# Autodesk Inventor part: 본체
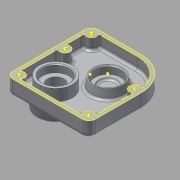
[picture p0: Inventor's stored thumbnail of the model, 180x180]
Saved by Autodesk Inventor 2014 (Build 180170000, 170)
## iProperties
Created: 2015-10
Part Number: 본체
Material: 알루미늄 6061
Document SubType Name: Modeling
Designer: youjin16
Density: 2.71 g/cm^3
Appearance: 알루미늄 - 평지
Mass: 265.675 g
Surface Area: 404.309 cm^2
Volume: 98.0352 cm^3
Author: youjin16
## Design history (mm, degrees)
sketch "스케치1"
  geometry: L1 (-42, 51.5)-(50, 51.5); L2 (50, 51.5)-(50, -43.5); L3 (42, -51.5)-(-42, -51.5); L4 (-50, -43.5)-(-50, 43.5); L5 (-50, 51.5)-(50, -51.5); L6 (50, 51.5)-(-50, -51.5); A1 r 8 centre (-42, 43.5) between (-42, 51.5) and (-50, 43.5); A2 r 8 centre (-42, -43.5) between (-50, -43.5) and (-42, -51.5); A3 r 8 centre (42, -43.5) between (42, -51.5) and (50, -43.5); 1 further point
  constraints: 12 end point, 6 point on circle, 6 point on line, 6 tangent, 3 centre point, 2 equal radius, 2 midpoint, 2 parallel, 1 horizontal, 1 perpendicular
  dimensions: "d0" = 100 distance of L5.end L6.end; "d1" = 103 distance of L6.end L5.start; "d2" = 8 radius of A1
extrude "돌출1" new body sketch "스케치1" distance "d3" = 18; taper "d4" = 0 deg
sketch "스케치2"
  geometry: L1 (50, 51.5)-(-42, 51.5) reference; L2 (-50, 43.5)-(-50, -43.5) reference; L3 (-42, -51.5)-(42, -51.5) reference; L4 (50, -43.5)-(50, 51.5) reference; L5 (-37.528, -47.5)-(37.528, -47.5); L6 (-46, -39.028)-(-46, 39.028); L7 (46, -39.028)-(46, 51.5); L8 (-37.528, 47.5)-(46, 47.5); L9 (-42, 17.5)-(-46, 17.5); L10 (-42, 5.5)-(-46, 5.5); L11 (42, 5.5)-(46, 5.5); L12 (42, 17.5)-(46, 17.5); A1 r 8 centre (-42, 43.5) between (-42, 51.5) and (-50, 43.5) reference; A2 r 8 centre (-42, -43.5) between (-50, -43.5) and (-42, -51.5) reference; A3 r 8 centre (42, -43.5) between (42, -51.5) and (50, -43.5) reference; A4 r 6 centre (-42, 43.5) between (-46, 39.028) and (-37.528, 47.5); A5 r 6 centre (-42, -43.5) between (-46, -39.028) and (-37.528, -47.5); A6 r 6 centre (42, -43.5) between (37.528, -47.5) and (46, -39.028); A7 r 6 centre (-42, 11.5) between (-42, 17.5) and (-42, 5.5); A8 r 6 centre (42, 11.5) between (42, 5.5) and (42, 17.5); 1 further point
  constraints: 16 end point, 10 point on circle, 6 perpendicular, 6 point on line, 5 centre point, 4 tangent, 3 coincident, 2 parallel, 2 vertical alignment
  dimensions: "d5" = 12 diameter of A4; "d6" = 12 diameter of A5; "d7" = 12 diameter of A6; "d8" = 4 distance between parallel lines of L3 L5; "d9" = 4 distance between parallel lines of L2 L6; "d10" = 4 distance between parallel lines of L8 L1; "d11" = 4 distance between parallel lines of L4 L7; "d16" = 12 diameter of A7; "d17" = 63 distance from line of L3 A7.centre; "d18" = 12 diameter of A8; "d19" = 63 distance from line of L3 A8.centre
extrude "돌출2" cut sketch "스케치2" distance "d12" = 4; taper "d13" = 0 deg
extrude "돌출3" join sketch "스케치2" stored distance "d20" = 4; taper "d21" = 0 deg
extrude "돌출4" join sketch "스케치2" distance "d22" = 4; taper "d23" = 0 deg
extrude "돌출5" join sketch "스케치2" distance "d24" = 4; taper "d25" = 0 deg
fillet "모깎기1" dims "d31" = 40
sketch "스케치5"
  geometry: L1 (46, 28.936)-(46, 17.5) reference; L2 (46, 17.5)-(42, 17.5) reference; L3 (42, 5.5)-(46, 5.5) reference; L4 (-37.528, 47.5)-(27.436, 47.5) reference; L5 (10, 51.5)-(-42, 51.5) reference; A1 r 6 centre (42, 11.5) between (42, 17.5) and (42, 5.5) reference; A2 r 40 centre (10, 11.5) between (27.436, 47.5) and (10, 51.5) reference; A3 r 36 centre (10, 11.5) between (10, 47.5) and (45.496, 5.5); A4 r 40 centre (10, 11.5) between (10, 51.5) and (46, 28.936); A5 r 36 centre (10, 11.5) between (45.496, 17.5) and (10, 47.5); A6 r 40 centre (10, 11.5) between (27.436, 47.5) and (10, 51.5); A7 r 40 centre (10, 11.5) between (46, 28.936) and (27.436, 47.5); A8 r 36 centre (10, 11.5) between (45.496, 5.5) and (45.688, 16.233); A9 r 36 centre (10, 11.5) between (45.688, 16.233) and (45.496, 17.5); 1 further point
  constraints: 15 point on circle, 7 centre point, 3 end point, 3 point on line, 2 coincident
  dimensions: "d32" = 72 diameter of A3
extrude "돌출7" join sketch "스케치5" stored distance "d33" = 10; taper "d34" = 0 deg
sketch "스케치6"
  geometry: C1 r 4 at (42, 43.5); C2 r 4 at (42, 11.5); C3 r 4 at (42, -43.5); C4 r 4 at (-42, -43.5); C5 r 4 at (-42, 11.5); A1 r 6 centre (42, 43.5) between (37.528, 47.5) and (46, 39.028) reference; A2 r 6 centre (42, -43.5) between (46, -39.028) and (37.528, -47.5) reference; A3 r 6 centre (42, 11.5) between (42, 17.5) and (42, 5.5) reference; A4 r 6 centre (-42, -43.5) between (-37.528, -47.5) and (-46, -39.028) reference; A5 r 6 centre (-42, 11.5) between (-42, 5.5) and (-42, 17.5) reference; 1 further point
  constraints: 5 centre point, 5 coincident
  dimensions: "d35" = 8 diameter of C1; "d36" = 8 diameter of C2; "d37" = 8 diameter of C3; "d38" = 8 diameter of C4; "d39" = 8 diameter of C5
extrude "돌출8" cut sketch "스케치6" distance "d40" = 4.4; taper "d41" = 0 deg
sketch "스케치7"
  geometry: C1 r 4 at (0, 0) reference; C2 r 4 at (0, 55) reference; C3 r 4 at (0, 87) reference; C4 r 4 at (-84, 55) reference; C5 r 4 at (-84, 0) reference; C6 r 2.25 at (0, 0); C7 r 2.25 at (0, 55); C8 r 2.25 at (0, 87); C9 r 2.25 at (-84, 55); C10 r 2.25 at (-84, 0); 1 further point
  constraints: 5 centre point, 5 coincident
  dimensions: "d42" = 4.5 diameter of C6; "d43" = 4.5 diameter of C7; "d44" = 4.5 diameter of C8; "d45" = 4.5 diameter of C9; "d46" = 4.5 diameter of C10
extrude "돌출9" cut sketch "스케치7" stored distance "d47" = 4.4; taper "d48" = 0 deg
sketch "스케치8"
  geometry: L1 (10, 51.5)-(-42, 51.5) reference; L2 (-50, 43.5)-(-50, -43.5) reference; L3 (-42, -51.5)-(42, -51.5) reference; L4 (50, -43.5)-(50, 11.5) reference; L5 (45.496, 17.5)-(42, 17.5) reference; L6 (42, 5.5)-(46, 5.5) reference; L7 (46, 5.5)-(46, -39.028) reference; L8 (37.528, -47.5)-(-37.528, -47.5) reference; L9 (-46, -39.028)-(-46, 5.5) reference; L10 (-46, 5.5)-(-42, 5.5) reference; L11 (-42, 17.5)-(-46, 17.5) reference; L12 (-46, 17.5)-(-46, 39.028) reference; L13 (-37.528, 47.5)-(10, 47.5) reference; C1 r 2.25 at (42, 11.5) reference; C2 r 2.25 at (-42, 11.5) reference; C3 r 2.25 at (-42, -43.5) reference; C4 r 2.25 at (-42, 43.5) reference; C5 r 2.25 at (42, -43.5) reference; A1 r 40 centre (10, 11.5) between (50, 11.5) and (10, 51.5) reference; A2 r 8 centre (-42, 43.5) between (-42, 51.5) and (-50, 43.5) reference; A3 r 8 centre (-42, -43.5) between (-50, -43.5) and (-42, -51.5) reference; A4 r 8 centre (42, -43.5) between (42, -51.5) and (50, -43.5) reference; A5 r 6 centre (42, 11.5) between (42, 17.5) and (42, 5.5) reference; A6 r 6 centre (42, -43.5) between (46, -39.028) and (37.528, -47.5) reference; A7 r 6 centre (-42, -43.5) between (-37.528, -47.5) and (-46, -39.028) reference; A8 r 6 centre (-42, 11.5) between (-42, 5.5) and (-42, 17.5) reference; A9 r 6 centre (-42, 43.5) between (-46, 39.028) and (-37.528, 47.5) reference; A10 r 36 centre (10, 11.5) between (45.496, 17.5) and (10, 47.5) reference; 1 further point
sketch "스케치9"
  geometry: 1 further point
sketch "스케치11"
  geometry: L1 (-50, 43.5)-(-50, -43.5) reference; L2 (-42, -51.5)-(42, -51.5) reference; C1 r 20 at (-20, -21.5); 1 further point
  constraints: 1 centre point
  dimensions: "d49" = 40 diameter of C1; "d50" = 30 distance from line of C1.centre L1; "d51" = 30 distance from line of C1.centre L2
extrude "돌출10" join sketch "스케치11" stored distance "d52" = 4.4; taper "d53" = 0 deg
sketch "스케치24"
  geometry: L1 (-37.528, 47.5)-(10, 47.5) reference; L2 (-46, 17.5)-(-46, 39.028) reference; L3 (-46, 17.5)-(-42, 17.5) reference; L4 (-42, 5.5)-(-46, 5.5) reference; L5 (-46, -39.028)-(-46, 5.5) reference; L6 (37.528, -47.5)-(-37.528, -47.5) reference; L7 (46, 5.5)-(46, -39.028) reference; L8 (46, 5.5)-(42, 5.5) reference; L9 (42, 17.5)-(45.496, 17.5) reference; C1 r 20 at (-20, -21.5) reference; C2 r 20 at (10, 11.5) reference; A1 r 36 centre (10, 11.5) between (45.496, 17.5) and (10, 47.5) reference; A2 r 6 centre (-42, 43.5) between (-46, 39.028) and (-37.528, 47.5) reference; A3 r 6 centre (-42, 11.5) between (-42, 5.5) and (-42, 17.5) reference; A4 r 6 centre (-42, -43.5) between (-37.528, -47.5) and (-46, -39.028) reference; A5 r 6 centre (42, -43.5) between (46, -39.028) and (37.528, -47.5) reference; A6 r 6 centre (42, 11.5) between (42, 17.5) and (42, 5.5) reference; 1 further point
sketch "스케치12"
  geometry: C1 r 20 at (0, 0) reference; C2 r 16 at (0, 0); 1 further point
  constraints: 1 centre point, 1 coincident
  dimensions: "d54" = 32 diameter of C2
extrude "돌출11" cut sketch "스케치12" distance "d55" = 9; taper "d56" = 0 deg
sketch "스케치13"
  geometry: C1 r 16 at (0, 0) reference; 1 further point
sketch "스케치14"
  geometry: C1 r 20 at (20, -21.5) reference; C2 r 25 at (20, -21.5); 1 further point
  constraints: 1 centre point, 1 coincident
  dimensions: "d57" = 50 diameter of C2
extrude "돌출12" join sketch "스케치14" distance "d58" = 15; taper "d59" = -10 deg
sketch "스케치15"
  geometry: C1 r 22.355 at (0, 0) reference; C2 r 14 at (0, 0); 1 further point
  constraints: 1 centre point, 1 coincident
  dimensions: "d60" = 28 diameter of C2
extrude "돌출13" cut sketch "스케치15" distance "d61" = 11; taper "d62" = 0 deg
sketch "스케치16"
  geometry: C1 r 14 at (0, 0) reference; C2 r 12 at (0, 0); 1 further point
  constraints: 1 centre point, 1 coincident
  dimensions: "d63" = 24 diameter of C2
extrude "돌출14" cut sketch "스케치16" distance "d64" = 2; taper "d65" = 0 deg
sketch "스케치17"
  geometry: C1 r 16 at (0, 0) reference; C2 r 10 at (0, 0); 1 further point
  constraints: 1 centre point, 1 coincident
  dimensions: "d66" = 20 diameter of C2
extrude "돌출15" cut sketch "스케치17" stored distance "d67" = 2; taper "d68" = 0 deg
sketch "스케치18"
  geometry: C1 r 22.355 at (0, 0) reference; A1 r 18 centre (0, 0) between (0, 18) and (18, 0); 3 further points
  constraints: 4 point on circle, 1 centre point, 1 coincident
  dimensions: "d69" = 36 diameter of A1
hole "구멍1" sketch "스케치18" at (0, 18), (18, 0), (0, -18), (-18, 0) diameter "d70" = 2.459; stored, may be unused: countersink angle "d74" = 90 deg, drill point angle "d76" = 118 deg; dims "d71" = 8, "d72" = 4, "d73" = 2, "d75" = 10
sketch "스케치19"
  geometry: 1 further point
node "작업 평면2"
node "작업 평면3"
node "작업 평면4"
sketch "스케치20"
  geometry: 1 further point
node "작업 평면5"
sketch "스케치23"
  geometry: 1 further point
node "작업 평면6"
sketch "스케치25"
  geometry: 1 further point
node "작업 평면7"
sketch "스케치26"
  geometry: 1 further point
sketch "스케치27"
  geometry: L1 (45.496, 17.5)-(42, 17.5) reference; L2 (42, 5.5)-(46, 5.5) reference; L3 (46, 5.5)-(46, -39.028) reference; L4 (37.528, -47.5)-(-37.528, -47.5) reference; L5 (-46, -39.028)-(-46, 5.5) reference; L6 (-46, 5.5)-(-42, 5.5) reference; L7 (-42, 17.5)-(-46, 17.5) reference; L8 (-46, 17.5)-(-46, 39.028) reference; L9 (-37.528, 47.5)-(10, 47.5) reference; C1 r 20 at (10, 11.5); C2 r 20 at (-20, -21.5) reference; C3 r 20 at (-20, -21.5) reference; A1 r 6 centre (42, 11.5) between (42, 17.5) and (42, 5.5) reference; A2 r 6 centre (42, -43.5) between (46, -39.028) and (37.528, -47.5) reference; A3 r 6 centre (-42, -43.5) between (-37.528, -47.5) and (-46, -39.028) reference; A4 r 6 centre (-42, 11.5) between (-42, 5.5) and (-42, 17.5) reference; A5 r 6 centre (-42, 43.5) between (-46, 39.028) and (-37.528, 47.5) reference; A6 r 36 centre (10, 11.5) between (45.496, 17.5) and (10, 47.5) reference; 1 further point
  constraints: 1 centre point, 1 coincident
  dimensions: "d91" = 40 diameter of C1
extrude "돌출19" cut sketch "스케치27" distance "d92" = 14; taper "d93" = 0 deg
sketch "스케치28"
  geometry: C1 r 20 at (10, 11.5); A1 r 36 centre (10, 11.5) between (45.496, 17.5) and (10, 47.5) reference; 1 further point
  constraints: 1 centre point, 1 coincident
  dimensions: "d94" = 40 diameter of C1
extrude "돌출20" join sketch "스케치28" distance "d95" = 11; taper "d96" = -10 deg
node "작업 평면8"
sketch "스케치29"
  geometry: C1 r 18.06 at (0, 0) reference; C2 r 16 at (0, 0); 1 further point
  constraints: 1 centre point, 1 coincident
  dimensions: "d98" = 32 diameter of C2
extrude "돌출21" cut sketch "스케치29" distance "d99" = 9; taper "d100" = 0 deg
sketch "스케치30"
  geometry: C1 r 16 at (0, 0) reference; C2 r 11 at (0, 0); 1 further point
  constraints: 1 centre point, 1 coincident
  dimensions: "d101" = 22 diameter of C2
extrude "돌출22" cut sketch "스케치30" distance "d102" = 2; taper "d103" = 0 deg
node "작업 평면9"
sketch "스케치32"
  geometry: 1 further point
sketch "스케치33"
  geometry: L1 (50, 43.5)-(50, -43.5) reference; L2 (-10, 51.5)-(42, 51.5) reference; 2 further points
  constraints: 1 other
  dimensions: "d107" = 40 distance from line of L1 point (10, 31.5); "d108" = 20 distance from line of L2 point (10, 31.5)
feature "엠보싱1" sketch "스케치33" dims "d109" = 0.5, "d110" = 0
fillet "모깎기4" dims "d113" = 3
node "작업 평면10"
fillet "모깎기5" dims "d115" = 3
fillet "모깎기6" dims "d116" = 0.3
chamfer "모따기1" distance "d117" = 1; stored, may be unused: second distance "d118" = 2, angle "d119" = 45 deg
fillet "모깎기7" dims "d120" = 3
fillet "모깎기8" dims "d121" = 3
chamfer "모따기2" distance "d126" = 1; stored, may be unused: second distance "d127" = 2, angle "d128" = 45 deg
chamfer "모따기3" distance "d130" = 1; stored, may be unused: second distance "d131" = 2, angle "d132" = 45 deg
fillet "모깎기10" dims "d133" = 3
node "솔리드1"
